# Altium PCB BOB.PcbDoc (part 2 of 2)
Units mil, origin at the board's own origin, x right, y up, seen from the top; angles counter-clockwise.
Board outline 7000 x 12000 mil, 6 copper layers (Top Layer, Int1 (GND), Int2 (Sign), Int3 (Sign), Int4 (GND2), Bottom Layer), stack 63.868 mil thick; 173 components, 165 nets, 617 pads, 174 vias.
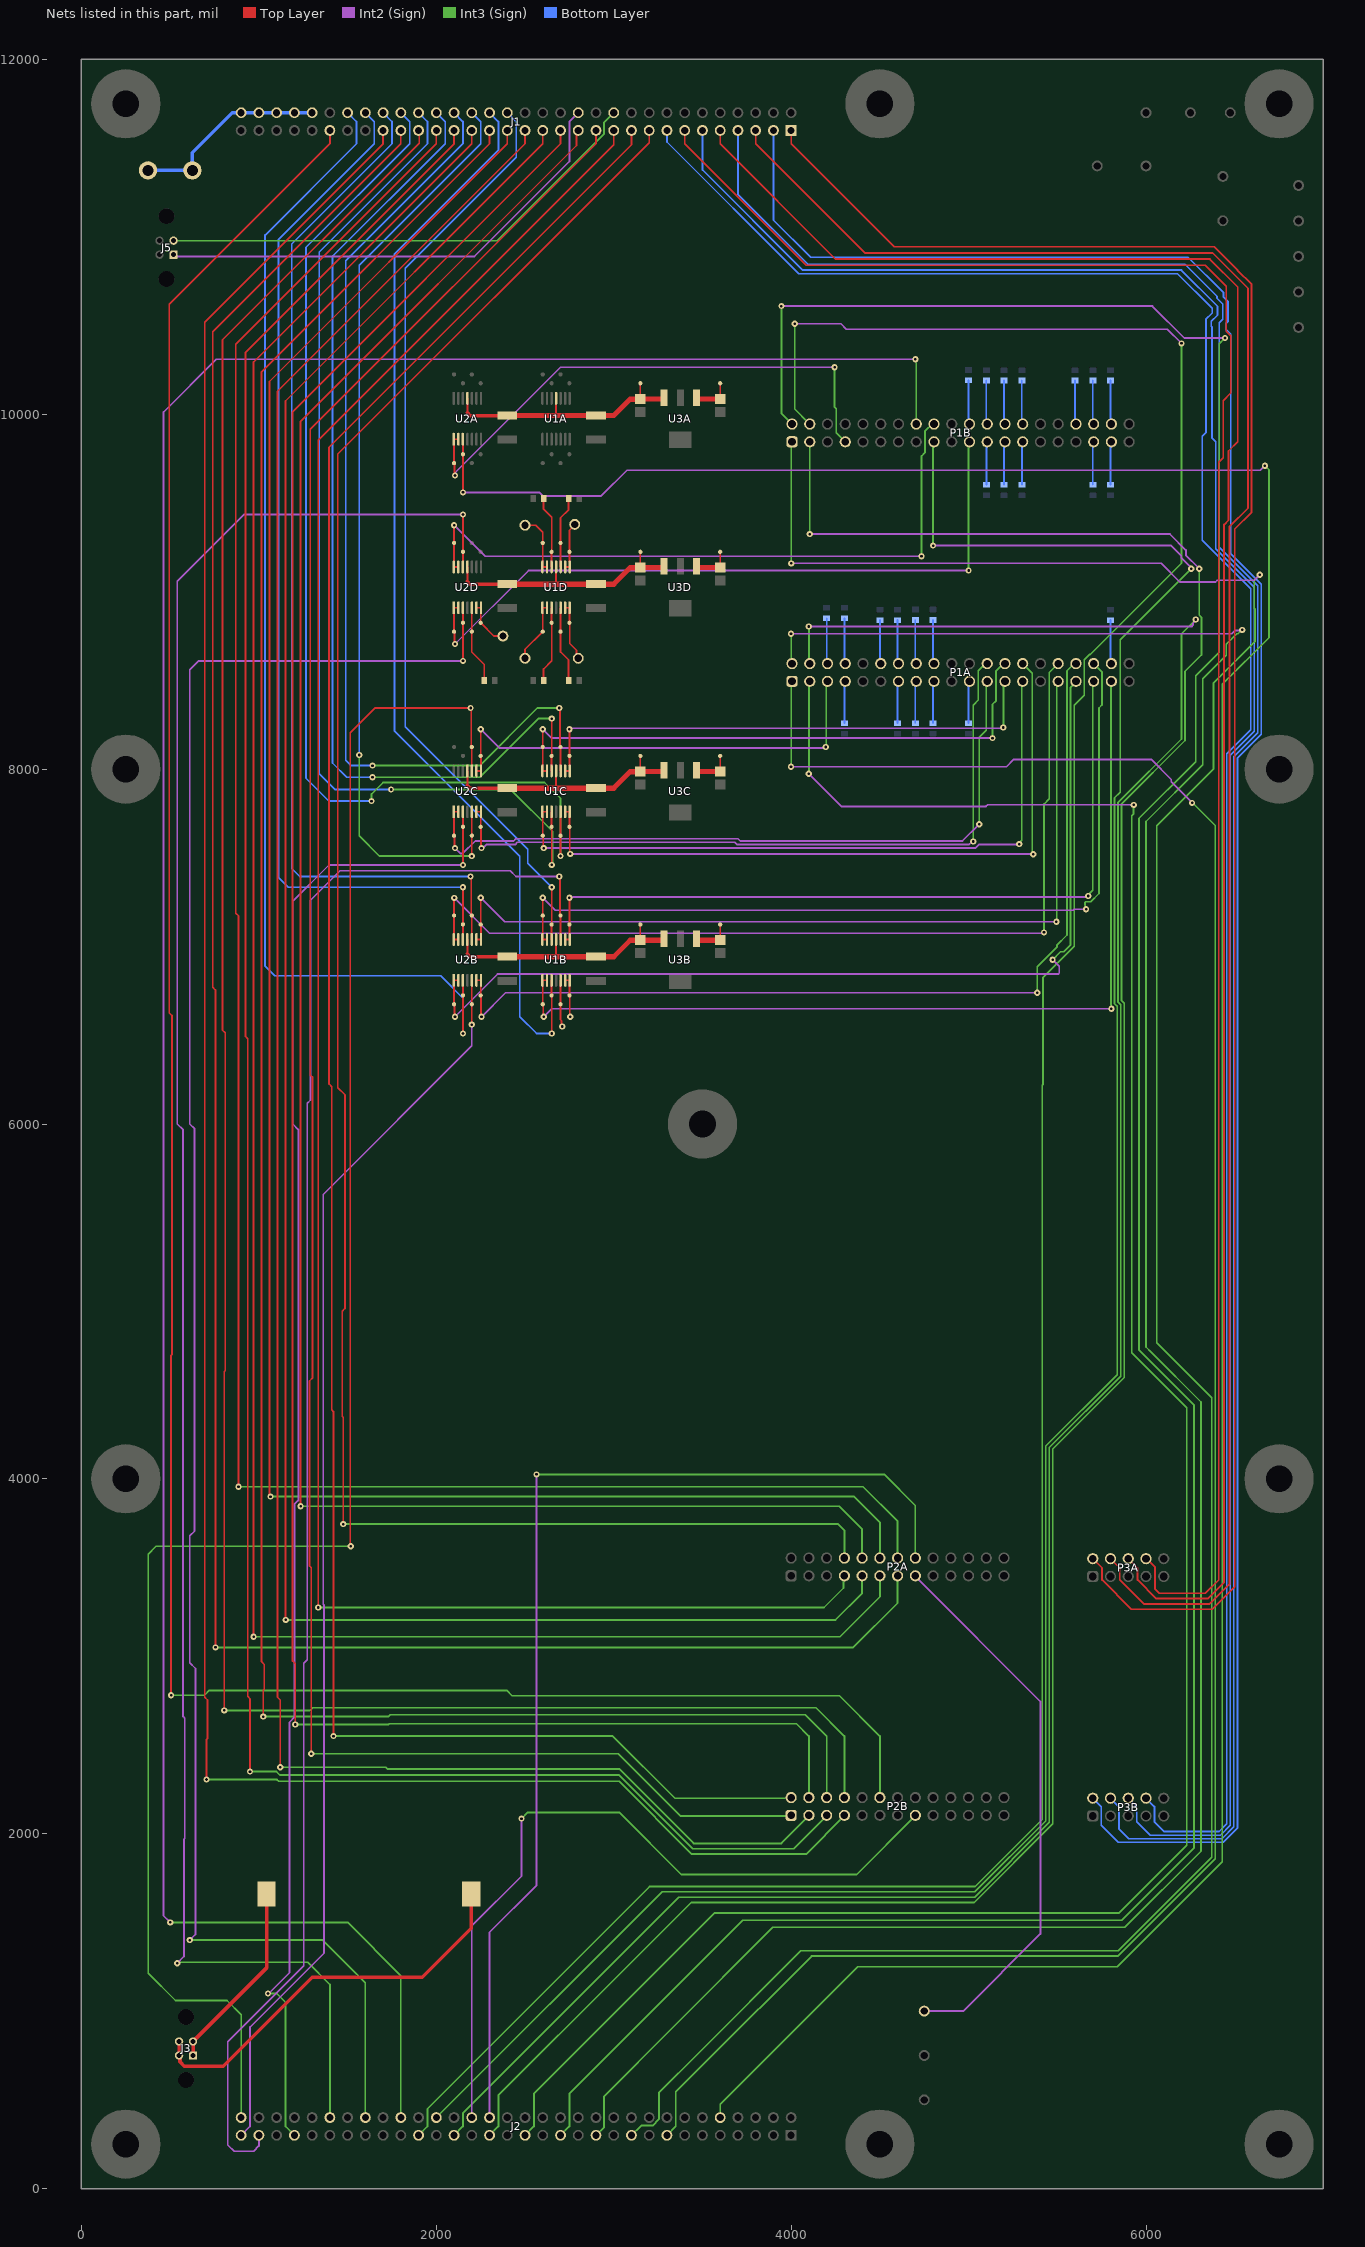
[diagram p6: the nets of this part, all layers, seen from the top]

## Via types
v1: diameter 35, hole 15, Top Layer to Bottom Layer, 157 vias
v2: diameter 25, hole 15, Top Layer to Bottom Layer, 17 vias

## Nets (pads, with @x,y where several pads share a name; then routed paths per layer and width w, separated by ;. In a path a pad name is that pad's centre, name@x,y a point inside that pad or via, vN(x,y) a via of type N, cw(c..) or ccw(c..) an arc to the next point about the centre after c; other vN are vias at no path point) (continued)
HPB_MEDIA_CURRENT: J2.64 TP6C.1 U2C.3 | length 10403.1
  Top Layer w10: v1(1517.5,3620) 1515,3622.5 1515,8205 1655.16,8345.16 v1(2193.23,8345.16) 2197.39,8340.99 2197.39,8127.61 2200.3,8124.7 2200.3,7990.45 U2C.3@2200.59,7990.16
  Int3 (Sign) w10: J2.64@900,400 900,980 820,1060 530,1060 375.86,1214.14 375.86,3575.86 420,3620 v1(1517.5,3620)
HPB_MEDIA_CURRENT_BUF: P1A.5 TP4C.1 U2C.1 U2C.2 | length 2628.8
  Top Layer w10: U2C.2@2226.18,7990.16 U2C.1@2251.77,7990.16 2251.05,7990.88 2251.05,8073.95 TP4C.1@2250,8075 v1(2250,8225)
  Int2 (Sign) w10: v1(2250,8225) 2355,8120 4190,8120 v1(4195,8125)
  Int3 (Sign) w10: v1(4195,8125) 4197.5,8127.5 4197.5,8497.5 P1A.5@4200,8500
HPB_SYNCBOX_CURRENT: J2.10 TP14A.1 U2A.10 | length 16357.4
  Top Layer w10: U2A.10@2149.41,9859.84 2149.7,9859.55 2149.7,9775.3 TP14A.1@2150,9775 v1(2150,9560)
  Int2 (Sign) w10: v1(2150,9560) 2580,9560 2600,9540 2930,9540 3075,9685 6645,9685 v1(6670,9710)
  Int3 (Sign) w10: J2.10@3600,400 3600,475 4105,980 4375,1250 5838.43,1250 6430,1841.57 6430,8478.28 6693.76,8742.05 6693.76,9686.24 v1(6670,9710)
HPB_SYNCBOX_CURRENT_BUF: P1B.7 TP12A.1 U2A.8 U2A.9 | length 3072.5
  Top Layer w10: v1(2105,9655) 2102.5,9657.5 2102.5,9722.5 TP12A.1@2100,9725 2100,9827.52 2098.23,9829.29 U2A.8@2098.23,9859.84 U2A.9@2123.82,9859.84
  Int2 (Sign) w10: v1(2105,9655) 2109.78,9659.78 2109.78,9674.78 2700,10265 v1(4245,10265)
  Int3 (Sign) w10: v1(4245,10265) 4245,10040 4254,10031 4254,9896 P1B.7@4300,9850
HPB_SYNCBOX_EN: J1.53 P2B.12 | length 13666.2
  Top Layer w10: v1(505,2780) 505,4696.32 510,4701.32 510,6610.88 495,6625.88 495,10620 1400,11525 J1.53@1400,11600
  Int3 (Sign) w10: v1(505,2780) 693.61,2780 721.11,2807.5 2396.54,2807.5 2426.54,2777.5 4272.5,2777.5 4500,2550 P2B.12@4500,2200
HPB_TEMP0: J1.44 TP13C.1 U1C.10 | length 5939.7
  Top Layer w10: U1C.10@2649.41,7759.84 2649.7,7759.55 2649.7,7675.3 TP13C.1@2650,7675 ; v1(2650.3,7460.3) TP13C.1@2650.3,7675.3
  Int3 (Sign) w10: v1(1745,7885) 2420,7885 2655,7650 2655,7465 v1(2650.3,7460.3)
  Bottom Layer w10: v1(1745,7885) 1430,7885 1340,7975 1340,8430 1340,10915 1950,11525 1950,11650 J1.44@1900,11700
HPB_TEMP0_F_BUF: P1A.27 TP11C.1 U1C.8 U1C.9 | length 3851.3
  Top Layer w10: v1(2605,7555) 2602.5,7557.5 2602.5,7622.5 TP11C.1@2600,7625 2600,7727.52 2598.23,7729.29 U1C.8@2598.23,7759.84 U1C.9@2623.82,7759.84
  Int2 (Sign) w10: v1(2605,7555) 5038.14,7555 5058.14,7575 5282.5,7575 v1(5285,7577.5)
  Int3 (Sign) w10: v1(5285,7577.5) 5285,7584.26 5300,7599.26 P1A.27@5300,8500
HPB_TEMP1: J1.46 TP17C.1 U1C.12 | length 6181
  Top Layer w10: TP17C.1@2700,7625 TP17C.1@2700.3,7625.3 ; v1(2700.3,7510.3) TP17C.1@2700.3,7625.3 ; U1C.12@2700.59,7759.84 2700.3,7759.55 TP17C.1@2700.3,7625.3
  Int3 (Sign) w10: v1(1635,7820) 1635,7860 1700,7925 2610,7925 2700.3,7834.7 v1(2700.3,7510.3)
  Bottom Layer w10: v1(1635,7820) 1395,7820 1265,7950 1265,8430 1265,10940 1850,11525 1850,11650 J1.46@1800,11700
HPB_TEMP1_F_BUF: P1A.28 TP15C.1 U1C.13 U1C.14 | length 3983.7
  Top Layer w10: U1C.13@2726.18,7759.84 U1C.14@2751.77,7759.84 2751.05,7759.12 2751.05,7676.05 TP15C.1@2750,7675 2752.5,7672.5 2752.5,7525 v1(2755,7522.5)
  Int2 (Sign) w10: v1(2755,7522.5) 2756.25,7521.25 5363.75,7521.25 v1(5365,7520)
  Int3 (Sign) w10: P1A.28@5300,8600 5358.5,8541.5 5358.5,7538.36 5360.22,7536.65 5360.22,7524.78 v1(5365,7520)
HPB_TEMP2: J1.48 TP6B.1 U2B.3 | length 5898.8
  Top Layer w10: v1(2192.93,7394.86) 2197.39,7390.4 2197.39,7179.08 TP6B.1@2200.74,7175.74 ; TP6B.1@2200,7175 2200.3,7174.7 2200.3,7040.45 U2B.3@2200.59,7040.16
  Bottom Layer w10: J1.48@1700,11700 1750,11650 1750,11525 1185,10960 1185,7440 1230.14,7394.86 v1(2192.93,7394.86)
HPB_TEMP2_F_BUF: P1A.31 TP4B.1 U2B.1 U2B.2 | length 4924.2
  Top Layer w10: U2B.2@2226.18,7040.16 U2B.1@2251.77,7040.16 2251.05,7040.88 2251.05,7123.95 TP4B.1@2250,7125 v1(2250,7275)
  Int2 (Sign) w10: v1(2250,7275) 2385,7140 v1(5495,7140)
  Int3 (Sign) w10: v1(5495,7140) 5497.5,7142.5 5497.5,8497.5 P1A.31@5500,8500
HPB_TEMP3: J1.50 TP10B.1 U2B.5 | length 5911.6
  Top Layer w10: U2B.5@2149.41,7040.16 2149.7,7040.45 2149.7,7124.7 TP10B.1@2150,7125 ; v1(2149.7,7334.7) 2149.85,7334.56 2149.85,7126.33 TP10B.1@2150.59,7125.59
  Bottom Layer w10: J1.50@1600,11700 1650,11650 1650,11525 1110,10985 1110,7390 1165.3,7334.7 v1(2149.7,7334.7)
HPB_TEMP3_F_BUF: P1A.32 TP8B.1 U2B.6 U2B.7 | length 5221.2
  Top Layer w10: v1(2100.48,7274.52) 2100.24,7274.28 2100.24,7175.24 2098.95,7173.95 2098.95,7040.88 U2B.7@2098.23,7040.16 U2B.6@2123.82,7040.16
  Int2 (Sign) w10: v1(2100.48,7274.52) 2300,7075 5420,7075 v1(5425,7080)
  Int3 (Sign) w10: v1(5425,7080) 5425,7802.91 5455,7832.91 5455,8545 5500,8590 P1A.32@5500,8600
HPB_TEMP4: J1.52 TP14B.1 U2B.10 | length 6733.6
  Top Layer w10: U2B.10@2149.41,6809.84 2149.7,6809.55 2149.7,6725.3 TP14B.1@2150,6725 ; v1(2150.15,6510.15) TP14B.1@2150.15,6725.15
  Bottom Layer w10: J1.52@1500,11700 1550,11650 1550,11525 1035,11010 1035,6890 1090,6835 2025,6835 2150.15,6709.85 v1(2150.15,6510.15)
HPB_TEMP4_F_BUF: P1A.33 TP12B.1 U2B.8 U2B.9 | length 5468.9
  Top Layer w10: v1(2105,6605) 2102.5,6607.5 2102.5,6672.5 TP12B.1@2100,6675 2100,6777.52 2098.23,6779.29 U2B.8@2098.23,6809.84 U2B.9@2123.82,6809.84
  Int2 (Sign) w10: v1(2105,6605) 2345,6845 5505.58,6845 5511.43,6850.86 5511.43,6888.57 v1(5473.72,6926.28)
  Int3 (Sign) w10: v1(5473.72,6926.28) 5517.91,6970.47 5535.59,6970.47 5575,7009.88 5575,8461.19 5600,8486.19 P1A.33@5600,8500
HPB_VICOR1_TEMP: J1.38 TP18C.1 U2C.12 | length 5312.2
  Top Layer w10: v1(2200,7510) TP18C.1@2200,7625 2200.3,7625.3 2200.3,7759.55 U2C.12@2200.59,7759.84
  Int3 (Sign) w10: v1(1565,8080) 1565,7625 1680,7510 v1(2200,7510)
  Bottom Layer w10: v1(1565,8080) 1565,8430 1565,10840 2250,11525 2250,11650 J1.38@2200,11700
HPB_VICOR1_TEMP_F_BUF: P1A.24 TP16C.1 U2C.13 U2C.14 | length 4068.2
  Top Layer w10: U2C.13@2226.18,7759.84 U2C.14@2251.77,7759.84 2251.77,7729.29 2250,7727.52 TP16C.1@2250,7675 2252.5,7672.5 2252.5,7557.5 v1(2255,7555)
  Int2 (Sign) w10: v1(2255,7555) 2260.96,7555 2280.96,7575 2443.86,7575 2456.36,7587.5 3682.78,7587.5 3695.28,7575 5001.52,7575 5019.02,7592.5 v1(5025.78,7592.5)
  Int3 (Sign) w10: v1(5025.78,7592.5) 5025.78,8360.78 5055,8390 5055,8555 P1A.24@5100,8600
HPB_VICOR2_TEMP: J1.40 TP5C.1 U1C.3 | length 5652.1
  Top Layer w10: v1(2693.23,8345.16) 2697.39,8340.99 2697.39,8127.61 TP5C.1@2700,8125 ; TP5C.1@2700.3,8124.7 2700.3,7990.45 U1C.3@2700.59,7990.16
  Int3 (Sign) w10: v1(1640,8020) 2245,8020 2570.16,8345.16 v1(2693.23,8345.16)
  Bottom Layer w10: v1(1640,8020) 1520,8020 1490,8050 1490,8430 1490,10865 2150,11525 2150,11650 J1.40@2100,11700
HPB_VICOR2_TEMP_F_BUF: P1A.25 TP3C.1 U1C.1 U1C.2 | length 2977.4
  Top Layer w10: U1C.2@2726.18,7990.16 U1C.1@2751.77,7990.16 2751.77,8020.71 2750,8022.48 TP3C.1@2750,8075 v1(2750,8225)
  Int2 (Sign) w10: v1(2750,8225) 2755,8230 5190,8230 v1(5195,8235)
  Int3 (Sign) w10: v1(5195,8235) 5197.5,8237.5 5197.5,8497.5 P1A.25@5200,8500
HPB_VICOR3_TEMP: J1.42 TP9C.1 U1C.5 | length 5648.1
  Top Layer w10: U1C.5@2649.41,7990.16 2649.7,7990.45 2649.7,8074.7 TP9C.1@2650,8075 ; v1(2650,8285) 2650,8076.77 TP9C.1@2650.89,8075.89
  Int3 (Sign) w10: v1(1640,7955) 2245,7955 2575,8285 v1(2650,8285)
  Bottom Layer w10: v1(1640,7955) 1495,7955 1415,8035 1415,8430 1415,10890 2050,11525 2050,11650 J1.42@2000,11700
HPB_VICOR3_TEMP_F_BUF: P1A.26 TP7C.1 U1C.6 U1C.7 | length 3268.8
  Top Layer w10: v1(2600,8225) TP7C.1@2600,8125 2600,8022.48 2598.23,8020.71 U1C.7@2598.23,7990.16 U1C.6@2623.82,7990.16
  Int2 (Sign) w10: v1(2600,8225) 2650,8175 v1(5135,8175)
  Int3 (Sign) w10: v1(5135,8175) 5135,8365.41 5155,8385.41 5155,8555 P1A.26@5200,8600
I2C_SCL: J1.26 J5.1 | length 2752.7
  Int2 (Sign) w10: J5.1@518.74,10900 528.74,10890 2215,10890 2750,11425 2750,11650 J1.26@2800,11700
I2C_SDA: J1.22 J5.2 | length 2817.7
  Int3 (Sign) w10: J5.2@518.74,10978.74 2343.1,10978.74 2945.51,11581.15 2945.51,11645.51 J1.22@3000,11700
IGB_TEMP_F: J2.57 TP14C.1 U2C.10 | length 8476.9
  Top Layer w10: U2C.10@2149.41,7759.84 2149.7,7759.55 2149.7,7675.3 TP14C.1@2150,7675 v1(2150,7460)
  Int2 (Sign) w10: v1(1050.88,1099.12) 1054.41,1099.12 1172.5,1217.21 1172.5,2628.46 1200,2655.96 1200,3855.96 1222.5,3878.46 1222.5,5968.5 1191,6000 1191,7256 1395,7460 v1(2150,7460)
  Int3 (Sign) w10: v1(1050.88,1099.12) 1100.88,1099.12 1150,1050 1150,350 J2.57@1200,300
IGB_TEMP_F_BUF: P1A.23 TP12C.1 U2C.8 U2C.9 | length 4105.9
  Top Layer w10: v1(2105,7555) 2102.5,7557.5 2102.5,7622.5 TP12C.1@2100,7625 2100,7727.52 2098.23,7729.29 U2C.8@2098.23,7759.84 U2C.9@2123.82,7759.84
  Int2 (Sign) w10: v1(2105,7555) 2135,7525 2150,7525 2220,7595 2435.58,7595 2448.08,7607.5 3700.29,7607.5 3712.79,7595 4965,7595 v1(5060,7690)
  Int3 (Sign) w10: v1(5060,7690) 5060,8180 5100,8220 P1A.23@5100,8500
INPUT_FET_LEFT_TEMP_F: J2.63 TP18B.1 U2B.12 | length 7052.9
  Top Layer w10: TP18B.1@2200,6675 2200.3,6675.3 2200.3,6809.55 U2B.12@2200.59,6809.84 ; v1(2200.15,6560.15) TP18B.1@2200.15,6675.15
  Int2 (Sign) w10: J2.63@900,300 950,350 950,909.85 1367.5,1327.35 1367.5,3288.46 1362.5,3293.46 1362.5,5602.5 2200.15,6440.15 v1(2200.15,6560.15)
INPUT_FET_LEFT_TEMP_F_BUF: P1A.34 TP16B.1 U2B.13 U2B.14 | length 5369.7
  Top Layer w10: U2B.13@2226.18,6809.84 U2B.14@2251.77,6809.84 2251.77,6779.29 2250,6777.52 TP16B.1@2250,6725 2252.5,6722.5 2252.5,6607.5 v1(2255,6605)
  Int2 (Sign) w10: v1(2255,6605) 2390,6740 v1(5387.5,6740)
  Int3 (Sign) w10: v1(5387.5,6740) 5387.5,6886.02 5497.79,6996.31 5497.79,7007.79 5555,7065 5555,8555 P1A.34@5600,8600
INPUT_FET_RIGHT_TEMP_F: J2.61 TP5B.1 U1B.3 | length 9313.1
  Top Layer w10: v1(2693.23,7395.16) 2697.39,7390.99 2697.39,7177.61 TP5B.1@2700,7175 ; TP5B.1@2700.3,7174.7 2700.3,7040.45 U1B.3@2700.59,7040.16
  Int2 (Sign) w10: J2.61@1000,300 1000,240 970,210 860,210 825,245 825,827.28 1252.5,1254.78 1252.5,2961.11 1272.5,2981.11 1272.5,6116.5 1291,6135 1291,7261 1457.36,7427.36 2416.86,7427.36 2449.07,7395.16 v1(2693.23,7395.16)
INPUT_FET_RIGHT_TEMP_F_BUF: P1A.35 TP3B.1 U1B.1 U1B.2 | length 4415.7
  Top Layer w10: U1B.2@2726.18,7040.16 U1B.1@2751.77,7040.16 2751.77,7070.71 2750,7072.48 TP3B.1@2750,7125 v1(2750,7275)
  Int2 (Sign) w10: v1(2750,7275) 2755,7280 5670,7280 v1(5675,7285)
  Int3 (Sign) w10: v1(5675,7285) 5675,7291.57 5700,7316.57 P1A.35@5700,8500
IPB1_BOARD_TEMP: J1.34 TP9B.1 U1B.5 | length 5280.9
  Top Layer w10: U1B.5@2649.41,7040.16 2649.7,7040.45 2649.7,7124.7 TP9B.1@2650,7125 ; v1(2650,7335) 2650,7126.77 TP9B.1@2650.89,7125.89
  Bottom Layer w10: J1.34@2400,11700 2450,11650 2450,11447.84 1825,10822.84 1825,8239.29 2515,7549.29 2515,7470 v1(2650,7335)
IPB1_BOARD_TEMP_BUF: P1A.36 TP7B.1 U1B.6 U1B.7 | length 4824.3
  Top Layer w10: v1(2600,7275) TP7B.1@2600,7175 2600,7072.48 2598.23,7070.71 U1B.7@2598.23,7040.16 U1B.6@2623.82,7040.16
  Int2 (Sign) w10: v1(2600,7275) 2670,7205 5590,7205 5595,7210 v1(5662.5,7210)
  Int3 (Sign) w10: v1(5662.5,7210) 5657.72,7214.78 5657.72,7234.61 5655.68,7236.64 5655.68,7246.64 5661.54,7252.5 5688.46,7252.5 5735,7299.04 5735,8345 5751.5,8361.5 5751.5,8548.5 P1A.36@5700,8600
IPB1_CHA_CURRENT_SET: J1.1 P3A.2 | length 11389.1
  Top Layer w10: J1.1@4000,11600 4000,11525 4580,10945 6385,10945 6515,10815 6515,10812.43 6595,10732.43 6595,9448.46 6500,9353.46 6500,3392.72 6372.28,3265 5917.85,3265 5752.52,3430.33 5752.52,3497.48 P3A.2@5700,3550
IPB1_CHA_FET_EN: J1.21 P2A.7 | length 12087.3
  Top Layer w10: v1(1335,3275) 1335,9854.91 3000,11519.91 J1.21@3000,11600
  Int3 (Sign) w10: v1(1335,3275) 4185,3275 4295,3385 4295,3445 P2A.7@4300,3450
IPB1_CHA_I: J2.15 P1A.1 | length 12729.4
  Int2 (Sign) w10: v1(3998.75,8013.75) 5213.75,8013.75 5255,8055 6028.46,8055 6141.84,7941.62 6141.84,7928.16 v1(6260,7810)
  Int3 (Sign) w10: J2.15@3300,300 3350,350 3350,545 3522.5,717.5 4115,1310 5841.86,1310 6390,1858.14 6390,7682.32 6262.32,7810 v1(6260,7810) ; v1@4000,8015 P1A.1@4000,8500
IPB1_CHA_RLY_EN: J1.17 P2A.8 | length 11606.3
  Top Layer w10: v1(1475,3745) 1475,4346.12 1470,4351.12 1470,4945.47 1485,4960.47 1485,6164.17 1445,6204.17 1445,9776.57 3200,11531.57 J1.17@3200,11600
  Int3 (Sign) w10: v1(1475,3745) 4265,3745 4300,3710 P2A.8@4300,3550
IPB1_CHB_CURRENT_SET: J1.5 P3A.4 | length 11396.5
  Top Layer w10: J1.5@3800,11600 3800,11525 4415,10910 6375,10910 6575,10710 6575,9470.89 6470,9365.89 6470,3405.15 6359.85,3295 5987.85,3295 5852.52,3430.33 5852.52,3497.48 P3A.4@5800,3550
IPB1_CHB_FET_EN: J1.29 P2A.9 | length 12402.2
  Top Layer w10: v1(1151,3205) 1150,3206 1150,10075 2600,11525 J1.29@2600,11600
  Int3 (Sign) w10: v1(1151,3205) 4250,3205 4400,3355 P2A.9@4400,3450
IPB1_CHB_I: J2.23 P1A.2 | length 14135.1
  Int2 (Sign) w10: v1(3998.75,8763.75) 6482.79,8763.75 6500,8780.96 6538.46,8780.96 v1(6542.5,8785)
  Int3 (Sign) w10: J2.23@2900,300 2945.51,345.51 2945.51,520.51 3332.5,907.5 3897.28,1472.28 5857.28,1472.28 5880.42,1472.28 6310,1901.86 6310,4433.22 6030,4713.22 6000,4743.22 6000,7705.15 6320,8025.15 6320,8509.71 6452.5,8642.21 6452.5,8704.04 6511.46,8763 6518.54,8763 6540.53,8785 v1(6542.5,8785) ; P1A.2@4000,8600 v1@4000,8765
IPB1_CHB_RLY_EN: J1.25 P2A.10 | length 11787.1
  Top Layer w10: v1(1235,3845) 1235,9960 2790.32,11515.32 2790.32,11590.32 J1.25@2800,11600
  Int3 (Sign) w10: v1(1235,3845) 4270,3845 4400,3715 P2A.10@4400,3550
IPB1_CHC_CURRENT_SET: J1.9 P3A.6 | length 11369.9
  Top Layer w10: J1.9@3600,11600 3600,11525 4250,10875 6360,10875 6517.5,10717.5 6517.5,9845.96 6465,9793.46 6465,9403.31 6440,9378.31 6440,3417.57 6347.43,3325 6057.85,3325 5952.52,3430.33 5952.52,3497.48 P3A.6@5900,3550
IPB1_CHC_FET_EN: J1.37 P2A.11 | length 12738.4
  Top Layer w10: v1(970,3110) 970,10295 2200,11525 J1.37@2200,11600
  Int3 (Sign) w10: v1(970,3110) 4275,3110 4500.86,3335.86 4500.86,3379.81 4500,3380.66 P2A.11@4500,3450
IPB1_CHC_I: J2.31 P1A.3 | length 12950.7
  Int2 (Sign) w10: v1(4098.75,7973.75) 4282.5,7790 5097.87,7790 5107.87,7800 5930,7800 v1(5931.27,7798.73)
  Int3 (Sign) w10: J2.31@2500,300 2550,350 2550,535 3127.5,1112.5 3567.28,1552.28 5847.28,1552.28 6230,1935 6230,4400 5920,4710 5920,7738.28 5930,7748.28 5930,7797.47 v1(5931.27,7798.73) ; v1@4100,7975 P1A.3@4100,8500
IPB1_CHC_RLY_EN: J1.33 P2A.12 | length 11957.2
  Top Layer w10: v1(1065,3900) 1060,3905 1060,10185 2400,11525 J1.33@2400,11600
  Int3 (Sign) w10: v1(1065,3900) 4355,3900 4500,3755 P2A.12@4500,3550
IPB1_CHD_CURRENT_SET: J1.13 P3A.8 | length 11385.8
  Top Layer w10: J1.13@3400,11600 3400,11525 4085,10840 6335,10840 6452.5,10722.5 6452.5,10468.46 6477.5,10443.46 6477.5,10120.04 6435,10077.54 6435,9754.11 6410,9729.11 6410,3430 6335,3355 6075,3355 6050,3380 6050,3505 6005,3550 P3A.8@6000,3550
IPB1_CHD_FET_EN: J1.45 P2A.13 | length 13093.8
  Top Layer w10: v1(755,3050) 755,6755.41 740,6770.41 740,10465 1800,11525 J1.45@1800,11600
  Int3 (Sign) w10: v1(755,3050) 4350,3050 4600,3300 P2A.13@4600,3450
IPB1_CHD_I: J2.39 P1A.4 | length 13675.6
  Int2 (Sign) w10: v1(4098.75,8803.75) 6257.31,8803.75 6264.38,8810.82 6264.38,8820.75 6280,8836.37 v1(6280,8843.14)
  Int3 (Sign) w10: J2.39@2100,300 2150,350 2150,425 2982.5,1257.5 3367.28,1642.28 5033.85,1642.28 5455,2063.43 5455,4176.72 5857.5,4579.22 5857.5,6671.75 5842.5,6686.75 5842.5,7812.5 6200,8170 6200,8763.14 v1(6280,8843.14) ; P1A.4@4100,8600 v1@4100,8805
IPB1_CHD_RLY_EN: J1.41 P2A.14 | length 12125
  Top Layer w10: v1(885,3955) 885,7172.91 870,7187.91 870,10395 2000,11525 J1.41@2000,11600
  Int3 (Sign) w10: v1(885,3955) 4405,3955 4600,3760 P2A.14@4600,3550
IPB1_RESET: J2.36 P2A.16 | length 6242.3
  Int2 (Sign) w10: J2.36@2300,400 2300,1445 2565,1710 v1(2565,4025)
  Int3 (Sign) w10: v1(2565,4025) 4525,4025 4700,3850 P2A.16@4700,3550
IPB2_BOARD_TEMP: J1.36 TP13B.1 U1B.10 | length 6169.5
  Top Layer w10: U1B.10@2649.41,6809.84 2649.7,6809.55 2649.7,6725.3 TP13B.1@2650,6725 v1(2650,6510)
  Bottom Layer w10: J1.36@2300,11700 2350,11650 2350,11489.26 1765,10904.26 1765,8214.29 2470,7509.29 2470,6605 2565,6510 v1(2650,6510)
IPB2_BOARD_TEMP_BUF: P1A.37 TP11B.1 U1B.8 U1B.9 | length 5303.9
  Top Layer w10: v1(2605,6605) 2602.5,6607.5 2602.5,6672.5 TP11B.1@2600,6675 2600,6777.52 2598.23,6779.29 U1B.8@2598.23,6809.84 U1B.9@2623.82,6809.84
  Int2 (Sign) w10: v1(2605,6605) 2650,6650 v1(5805,6650)
  Int3 (Sign) w10: P1A.37@5800,8500 5802.5,8497.5 5802.5,6652.5 v1(5805,6650)
IPB2_CHA_CURRENT_SET: J1.3 P3B.2 | length 13031
  Bottom Layer w10: J1.3@3900,11600 3900,11095 4110,10885 6236.57,10885 6437.18,10684.39 6437.18,10660.1 6462.82,10634.45 6462.82,10523.79 6452.5,10513.46 6452.5,10475.89 6477.5,10450.89 6477.5,9214.07 6650,9041.57 6650,8196.98 6515,8061.98 6515,2030.15 6436.49,1951.64 5843.36,1951.64 5747.48,2047.52 5747.48,2152.52 P3B.2@5700,2200
IPB2_CHA_FET_EN: J1.23 P2B.1 | length 12683.4
  Top Layer w10: v1(1295,2450) 1295,3499.04 1285,3509.04 1285,4551.32 1302.5,4568.82 1302.5,6263.38 1290,6275.88 1290,9915 2900,11525 J1.23@2900,11600
  Int3 (Sign) w10: v1(1295,2450) 3025,2450 3375,2100 P2B.1@4000,2100
IPB2_CHA_I: J2.19 P1B.1 | length 15001.3
  Int2 (Sign) w10: v1(4000,9160) 6085,9160 6190,9055 6391.62,9055 6401.62,9065 6610,9065 v1(6641.26,9096.26)
  Int3 (Sign) w10: J2.19@3100,300 3154.49,354.49 3218.85,354.49 3254.49,390.12 3254.49,539.49 3477.5,762.5 4055,1340 5843.58,1340 6370,1866.42 6370,4458.08 6060,4768.08 6060,7680.29 6380,8000.29 6380,8484.85 6615,8719.85 6615,8901.71 6610,8906.71 6610,9065 v1(6641.26,9096.26) ; v1(4000,9160) P1B.1@4000,9850
IPB2_CHA_RLY_EN: J1.19 P2B.2 | length 12491.6
  Top Layer w10: v1(1420,2550) 1420,4378.8 1410,4388.8 1410,6210.84 1395,6225.84 1395,9814.91 3100,11519.91 J1.19@3100,11600
  Int3 (Sign) w10: v1(1420,2550) 2995,2550 3345,2200 P2B.2@4000,2200
IPB2_CHB_CURRENT_SET: J1.7 P3B.4 | length 12983.2
  Bottom Layer w10: J1.7@3700,11600 3700,11240 4095,10845 6220,10845 6400,10665 6400,10654.85 6432.82,10622.03 6432.82,10536.21 6412.5,10515.89 6412.5,9854.5 6412.82,9854.17 6412.82,9250.46 6630,9033.28 6630,8205.27 6520,8095.27 6495,8070.27 6495,2038.43 6428.21,1971.64 5903.36,1971.64 5847.48,2027.52 5847.48,2152.52 P3B.4@5800,2200
IPB2_CHB_FET_EN: J1.31 P2B.3 | length 13031.4
  Top Layer w10: v1(1120,2375) 1120,2753.61 1105,2768.61 1105,10130 2500,11525 J1.31@2500,11600
  Int3 (Sign) w10: v1(1120,2375) 1714.3,2375 1724.3,2365 3030,2365 3450,1945 3945,1945 P2B.3@4100,2100
IPB2_CHB_I: J2.27 P1B.2 | length 16447
  Int2 (Sign) w10: v1(3945,10610) 6035.96,10610 6215.96,10430 v1(6445,10430)
  Int3 (Sign) w10: J2.27@2700,300 2750,350 2750,535 3227.5,1012.5 3727.28,1512.28 5448.85,1512.28 5863.85,1512.28 6270,1918.43 6270,4416.66 5990,4696.66 5960,4726.66 5960,7721.72 6280,8041.72 6280,8526.27 6412.5,8658.77 6412.5,10397.5 v1(6445,10430) ; v1(3945,10610) 3945,10005 P1B.2@4000,9950
IPB2_CHB_RLY_EN: J1.27 P2B.4 | length 12892.7
  Top Layer w10: v1(1205,2615) 1205,2958.61 1190,2973.61 1190,10015 2700,11525 J1.27@2700,11600
  Int3 (Sign) w10: v1(1205,2615) 1729.3,2615 1734.3,2620 4030,2620 4100,2550 P2B.4@4100,2200
IPB2_CHC_CURRENT_SET: J1.11 P3B.6 | length 12911
  Bottom Layer w10: J1.11@3500,11600 3500,11377.43 4064.7,10812.72 6199.7,10812.72 6402.82,10609.6 6402.82,10558.46 6367.82,10523.46 6367.82,10496.54 6372.5,10491.86 6372.5,9866.21 6392.82,9845.89 6392.82,9242.17 6610,9025 6610,8213.55 6500,8103.55 6475,8078.55 6475,2046.72 6419.93,1991.64 6023.36,1991.64 5947.48,2067.52 5947.48,2152.52 P3B.6@5900,2200
IPB2_CHC_FET_EN: J1.39 P2B.5 | length 13253.9
  Top Layer w10: v1(950,2350) 950,2761.11 937.5,2773.61 937.5,6480.88 925,6493.38 925,10350 2100,11525 J1.39@2100,11600
  Int3 (Sign) w10: v1(950,2350) 1099.04,2350 1119.04,2330 3030,2330 3445,1915 4015,1915 P2B.5@4200,2100
IPB2_CHC_I: J2.35 P1B.3 | length 14260.8
  Int2 (Sign) w10: v1(4105,9325) 6135,9325 6225.11,9234.89 6225.11,9205.85 6300,9130.96 v1(6300,9130)
  Int3 (Sign) w10: J2.35@2300,300 2350,350 2350,525 3032.5,1207.5 3437.28,1612.28 5032.13,1612.28 5475,2055.15 5475,4168.43 5877.5,4570.93 5877.5,6680.03 5862.5,6695.03 5862.5,7804.22 6220,8161.72 6220,8551.13 6312.5,8643.63 6312.5,8856.6 6300,8869.1 v1(6300,9130) ; v1(4105,9325) P1B.3@4105,9848.59
IPB2_CHC_RLY_EN: J1.35 P2B.6 | length 13059.4
  Top Layer w10: v1(1025,2660) 1025,2807.69 1030,2812.69 1030,2953.61 1015,2968.61 1015,10240 2300,11525 J1.35@2300,11600
  Int3 (Sign) w10: v1(1025,2660) 1729.3,2660 1739.3,2670 4080,2670 4200,2550 P2B.6@4200,2200
IPB2_CHD_CURRENT_SET: J1.15 P3B.8 | length 12860.9
  Bottom Layer w10: J1.15@3300,11600 3300,11535 4042.28,10792.72 6177.28,10792.72 6372.82,10597.18 6372.82,10570.89 6337.82,10535.89 6337.82,9896.82 6317.5,9876.5 6317.5,9289.21 6590,9016.71 6590,8221.84 6480,8111.84 6455,8086.84 6455,2055 6411.64,2011.64 6103.36,2011.64 6047.48,2067.52 6047.48,2152.52 P3B.8@6000,2200
IPB2_CHD_FET_EN: J1.47 P2B.7 | length 13577.6
  Top Layer w10: v1(705,2305) 705,2530.19 710,2535.19 710,2753.61 695,2768.61 695,10520 1700,11525 J1.47@1700,11600
  Int3 (Sign) w10: v1(705,2305) 1101.61,2305 1111.61,2295 3030,2295 3440,1885 4085,1885 P2B.7@4300,2100
IPB2_CHD_I: J2.43 P1B.4 | length 15776.7
  Int2 (Sign) w10: v1(4020,10510) 4280.96,10510 4310.96,10480 6120,10480 v1(6200,10400)
  Int3 (Sign) w10: J2.43@1900,300 1950,350 1950,450 2870,1370 3202.28,1702.28 5037.28,1702.28 5415,2080 5415,6217.81 5420,6222.81 5420,6826.6 5595,7001.6 5595,8360 5651.5,8416.5 5651.5,8615.86 5681.15,8645.51 5684.56,8645.51 6200,9160.95 v1(6200,10400) ; v1(4020,10510) 4020,10030 P1B.4@4100,9950
IPB2_CHD_RLY_EN: J1.43 P2B.8 | length 13291.1
  Top Layer w10: v1(805,2695) 805,4605.07 810,4610.07 810,6513.38 795,6528.38 795,10420 1903.14,11528.14 1903.14,11596.86 J1.43@1900,11600
  Int3 (Sign) w10: v1(805,2695) 1288.03,2695 1303.03,2710 4140,2710 4300,2550 P2B.8@4300,2200
IPB2_RESET: J2.38 P2B.15 | length 4317.1
  Int2 (Sign) w10: J2.38@2200,400 2200,1480 2480,1760 v1(2480,2085)
  Int3 (Sign) w10: v1(2480,2085) 2515,2120 3030,2120 3380,1770 4370,1770 P2B.15@4700,2100
MVC_L_CURRENT: J2.46 P1B.16 | length 15480.1
  Int2 (Sign) w10: v1(500,1500) 462.5,1537.5 462.5,10012.5 760,10310 v1(4700,10310)
  Int3 (Sign) w10: v1(500,1500) 1500,1500 1800,1200 J2.46@1800,400 ; v1(4700,10310) 4700,10303.24 4705,10298.24 P1B.16@4705,9945
MVC_L_VOLTAGE: J2.54 TP10D.1 U2D.5 | length 11549
  Top Layer w10: U2D.5@2149.41,9140.16 2149.7,9140.45 2149.7,9224.7 TP10D.1@2150,9225 ; v1(2150,9435) 2150,9226.77 TP10D.1@2150.89,9225.89
  Int2 (Sign) w10: v1(540,1270) 577.5,1307.5 577.5,1967.98 582.5,1972.98 582.5,2651.04 572.5,2661.04 572.5,5967.5 540,6000 540,8940 540,9060 915,9435 v1(2150,9435)
  Int3 (Sign) w10: v1(540,1270) 545,1275 1275,1275 1400,1150 J2.54@1400,400
MVC_L_VOLTAGE_BUF: P1B.18 TP8D.1 U2D.6 U2D.7 | length 3745.4
  Top Layer w10: TP8D.1@2100,9275 2098.95,9273.95 2098.95,9140.88 U2D.7@2098.23,9140.16 U2D.6@2123.82,9140.16 ; TP8D.1@2100.36,9275.36 v1(2100.36,9375.36)
  Int2 (Sign) w10: v1(2100.36,9375.36) 2275.72,9200 v1(4735,9200)
  Int3 (Sign) w10: v1(4735,9200) 4735,9765 4754,9784 4754,9904 P1B.18@4800,9950
MVC_R_CURRENT: J2.42 P1B.17 | length 13646.9
  Int2 (Sign) w10: v1(4800,9260) 6142.5,9260 6198.86,9203.64 6198.86,9191.14 6255,9135 v1(6255,9130)
  Int3 (Sign) w10: J2.42@2000,400 3272.28,1672.28 5035.56,1672.28 5435,2071.72 5435,4185 5837.5,4587.5 5837.5,6663.46 5822.5,6678.46 5822.5,7838.06 5855,7870.56 5855,8730 v1(6255,9130) ; v1(4800,9260) P1B.17@4800,9850
MVC_R_VOLTAGE: J2.50 TP14D.1 U2D.10 | length 10920.3
  Top Layer w10: U2D.10@2149.41,8909.84 2149.7,8909.55 2149.7,8825.3 TP14D.1@2150,8825 ; v1(2150.3,8610.3) TP14D.1@2150.3,8825.3
  Int2 (Sign) w10: v1(610,1400) 642.5,1432.5 642.5,2931.11 610,2963.61 610,3678.27 637.5,3705.77 637.5,5972.5 610,6000 610,8560 660.29,8610.3 v1(2150.3,8610.3)
  Int3 (Sign) w10: v1(610,1400) 1360,1400 1600,1160 J2.50@1600,400
MVC_R_VOLTAGE_BUF: P1B.21 TP12D.1 U2D.8 U2D.9 | length 4029.6
  Top Layer w10: TP12D.1@2100,8775 2100,8877.52 2098.23,8879.29 U2D.8@2098.23,8909.84 U2D.9@2123.82,8909.84 ; TP12D.1@2100.36,8775.36 2102.61,8773.12 2102.61,8708.12 v1(2105.36,8705.36)
  Int2 (Sign) w10: v1(2105.36,8705.36) 2520,9120 v1(5000,9120)
  Int3 (Sign) w10: v1(5000,9120) P1B.21@5000,9850
NetBT1_1: BT1.1 J3.1 J3.2 | length 1119.5
  Top Layer w20: J3.1@628.74,750 J3.2@628.74,828.74 1043.23,1243.23 BT1.1@1043.23,1660 BT1.1@1070,1686.77
NetBT1_2: BT1.2 J3.3 J3.4 | length 2315.8
  Top Layer w20: J3.4@550,828.74 J3.3@550,750 555.21,744.79 555.21,714.79 580,690 800,690 1300,1190 1920,1190 2196.77,1466.77 BT1.2@2196.77,1660 BT1.2@2220,1683.23
NetC1A_2: C1A.2 TP19A.1 U3A.1 | length 228
  Top Layer w10: C1A.2@3600,10086.42 TP19A.1@3600,10175
  Top Layer w30: U3A.1@3465.55,10094.09 3465.55,10091.1 3470.24,10086.42 C1A.2@3600,10086.42
NetC1B_2: C1B.2 TP19B.1 U3B.1 | length 228
  Top Layer w10: C1B.2@3600,7036.42 TP19B.1@3600,7125
  Top Layer w30: U3B.1@3465.55,7044.09 3465.55,7041.1 3470.24,7036.42 C1B.2@3600,7036.42
NetC1C_2: C1C.2 TP19C.1 U3C.1 | length 228
  Top Layer w10: C1C.2@3600,7986.42 TP19C.1@3600,8075
  Top Layer w30: U3C.1@3465.55,7994.09 3465.55,7991.1 3470.24,7986.42 C1C.2@3600,7986.42
NetC1D_2: C1D.2 TP19D.1 U3D.1 | length 228
  Top Layer w10: C1D.2@3600,9136.42 TP19D.1@3600,9225
  Top Layer w30: U3D.1@3465.55,9144.09 3465.55,9141.1 3470.24,9136.42 C1D.2@3600,9136.42
NetC2A_2: C2A.2 C3A.1 C4A.1 TP20A.1 U1A.4 U2A.4 U3A.3 | length 1426.2
  Top Layer w10: 2175,10010 U2A.4@2175,10090.16 ; 2675,9992.91 U1A.4@2675,10090.16 ; C2A.2@3150,10086.42 TP20A.1@3150,10175
  Top Layer w20: 2175,10010 2192.09,9992.91 C4A.1@2400,9992.91
  Top Layer w30: C4A.1@2400,9992.91 2675,9992.91 C3A.1@2900,9992.91 3000.12,9992.91 3093.05,10085.84 3149.42,10085.84 C2A.2@3150,10086.42 3279.76,10086.42 3284.45,10091.1 U3A.3@3284.45,10094.09
NetC2B_2: C2B.2 C3B.1 C4B.1 TP20B.1 U1B.4 U2B.4 U3B.3 | length 1428.2
  Top Layer w10: 2175,6960 U2B.4@2175,7040.16 ; 2670,6942.91 2675,6947.91 U1B.4@2675,7040.16 ; C2B.2@3150,7036.42 TP20B.1@3150,7125
  Top Layer w20: 2175,6960 2192.09,6942.91 C4B.1@2400,6942.91
  Top Layer w30: C4B.1@2400,6942.91 2670,6942.91 C3B.1@2900,6942.91 3000.12,6942.91 3093.05,7035.84 3149.42,7035.84 C2B.2@3150,7036.42 3279.76,7036.42 3284.45,7041.1 U3B.3@3284.45,7044.09
NetC2C_2: C2C.2 C3C.1 C4C.1 TP20C.1 U1C.4 U2C.4 U3C.3 | length 1426.2
  Top Layer w10: 2175,7910 U2C.4@2175,7990.16 ; 2675,7892.91 U1C.4@2675,7990.16 ; C2C.2@3150,7986.42 TP20C.1@3150,8075
  Top Layer w20: 2175,7910 2192.09,7892.91 C4C.1@2400,7892.91
  Top Layer w30: C4C.1@2400,7892.91 2675,7892.91 C3C.1@2900,7892.91 3000.12,7892.91 3093.05,7985.84 3149.42,7985.84 C2C.2@3150,7986.42 3279.76,7986.42 3284.45,7991.1 U3C.3@3284.45,7994.09
NetC2D_2: C2D.2 C3D.1 C4D.1 TP20D.1 U1D.4 U2D.4 U3D.3 | length 1426.2
  Top Layer w10: 2175,9060 U2D.4@2175,9140.16 ; 2675,9042.91 U1D.4@2675,9140.16 ; C2D.2@3150,9136.42 TP20D.1@3150,9225
  Top Layer w20: 2175,9060 2192.09,9042.91 C4D.1@2400,9042.91
  Top Layer w30: C4D.1@2400,9042.91 2675,9042.91 C3D.1@2900,9042.91 3000.12,9042.91 3093.05,9135.84 3149.42,9135.84 C2D.2@3150,9136.42 3279.76,9136.42 3284.45,9141.1 U3D.3@3284.45,9144.09
NetJ19_1: J19.1 P2A.15 | length 3142.2
  Int2 (Sign) w10: P2A.15@4700,3450 5405,2745 5405,1435 4970,1000 J19.1@4750,1000
NetP1A_6: P1A.6 R2.1 | length 240.5
  Bottom Layer w10: P1A.6@4200,8610 R2.1@4200,8850.47
NetP1A_7: P1A.7 R3.1 | length 240.5
  Bottom Layer w10: R3.1@4300,8259.53 P1A.7@4300,8500
NetP1A_8: P1A.8 R4.1 | length 240.5
  Bottom Layer w10: P1A.8@4300,8610.47 R4.1@4300,8850.94
NetP1A_12: P1A.12 R5.1 | length 240.5
  Bottom Layer w10: P1A.12@4500,8600 R5.1@4500,8840.47
NetP1A_13: P1A.13 R6.1 | length 240.5
  Bottom Layer w10: R6.1@4600,8259.53 P1A.13@4600,8500
NetP1A_14: P1A.14 R7.1 | length 240.5
  Bottom Layer w10: P1A.14@4600,8600 R7.1@4600,8840.47
NetP1A_15: P1A.15 R8.1 | length 240.5
  Bottom Layer w10: R8.1@4700,8259.06 P1A.15@4700,8499.53
NetP1A_16: P1A.16 R9.1 | length 240.5
  Bottom Layer w10: P1A.16@4700,8600.47 R9.1@4700,8840.94
NetP1A_17: P1A.17 R10.1 | length 240.5
  Bottom Layer w10: R10.1@4800,8259.06 P1A.17@4800,8499.53
NetP1A_18: P1A.18 R11.1 | length 240.5
  Bottom Layer w10: P1A.18@4800,8600.47 R11.1@4800,8840.94
NetP1A_21: P1A.21 R12.1 | length 240.5
  Bottom Layer w10: R12.1@5000,8259.53 P1A.21@5000,8500
NetP1A_38: P1A.38 R24.1 | length 240.5
  Bottom Layer w10: P1A.38@5800,8600 R24.1@5800,8840.47
NetP1B_22: P1B.22 R13.2 | length 240.9
  Bottom Layer w10: P1B.22@5000,9950 R13.2@5000,10190.94
NetP1B_23: P1B.23 R14.2 | length 240.5
  Bottom Layer w10: R14.2@5100.33,9604.02 P1B.23@5100.33,9844.49
NetP1B_24: P1B.24 R15.2 | length 240.9
  Bottom Layer w10: P1B.24@5100,9949.53 R15.2@5100,10190.47
NetP1B_25: P1B.25 R16.2 | length 240.5
  Bottom Layer w10: R16.2@5200.33,9603.54 P1B.25@5200.33,9844.02
NetP1B_26: P1B.26 R17.2 | length 240.9
  Bottom Layer w10: P1B.26@5200,9949.53 R17.2@5200,10190.47
NetP1B_27: P1B.27 R18.2 | length 240.5
  Bottom Layer w10: R18.2@5300.33,9604.02 P1B.27@5300.33,9844.49
NetP1B_28: P1B.28 R19.2 | length 240.9
  Bottom Layer w10: P1B.28@5300,9949.53 R19.2@5300,10190.47
NetP1B_34: P1B.34 R20.2 | length 240.9
  Bottom Layer w10: P1B.34@5600,9949.53 R20.2@5600,10190.47
NetP1B_35: P1B.35 R21.2 | length 240.5
  Bottom Layer w10: R21.2@5700.33,9604.02 P1B.35@5700.33,9844.49
NetP1B_36: P1B.36 R22.2 | length 240.9
  Bottom Layer w10: P1B.36@5700,9949.53 R22.2@5700,10190.47
NetP1B_37: P1B.37 R23.2 | length 240.5
  Bottom Layer w10: R23.2@5800.33,9604.02 P1B.37@5800.33,9844.49
NetP1B_38: P1B.38 R25.2 | length 240.9
  Bottom Layer w10: P1B.38@5800,9949.53 R25.2@5800,10190.47
NetR1_2: R1.2 TP17D.1 U1D.12 | length 429.1
  Top Layer w10: TP17D.1@2700,8775 TP17D.1@2700.3,8775.3 ; U1D.12@2700.59,8909.84 2700.3,8909.55 TP17D.1@2700.3,8775.3 ; R1.2@2745.47,8500 2745.47,8615.12 2700.3,8660.3 TP17D.1@2700.3,8775.3
NetR26_2: R26.2 TP13D.1 U1D.10 | length 429.3
  Top Layer w10: R26.2@2604.53,8500 2604.53,8564.53 2650.3,8610.3 TP13D.1@2650.3,8825.3 ; U1D.10@2649.41,8909.84 2649.7,8909.55 2649.7,8825.3 TP13D.1@2650,8825
NetR27_2: R27.2 TP9D.1 U1D.5 | length 403.6
  Top Layer w10: R27.2@2604.53,9525 2604.53,9465.47 2650,9420 2650,9226.18 TP9D.1@2650.59,9225.59 ; U1D.5@2649.41,9140.16 2649.7,9140.45 2649.7,9224.7 TP9D.1@2650,9225
NetR28_2: R28.2 TP5D.1 U1D.3 | length 403.5
  Top Layer w10: TP5D.1@2700,9275 2700.3,9274.7 2700.3,9140.45 U1D.3@2700.59,9140.16 ; TP5D.1@2700.74,9275.74 2700,9276.48 2700,9416 2745.47,9461.47 R28.2@2745.47,9525
NetR29_2: R29.2 TP18D.1 U2D.12 | length 439.5
  Top Layer w10: TP18D.1@2200,8775 TP18D.1@2200.3,8775.3 ; U2D.12@2200.59,8909.84 2200.3,8909.55 TP18D.1@2200.3,8775.3 ; R29.2@2270.47,8500 2270.47,8590.12 2200.3,8660.3 TP18D.1@2200.3,8775.3
NetTP3D_1: TP3D.1 TP22.1 U1D.1 U1D.2 | length 278.6
  Top Layer w10: U1D.2@2726.18,9140.16 U1D.1@2751.77,9140.16 2751.77,9170.71 2750,9172.48 TP3D.1@2750,9225 2750,9345.08 2780,9375.08 TP22.1@2780,9380
NetTP7D_1: TP7D.1 TP23.1 U1D.6 U1D.7 | length 337.7
  Top Layer w10: TP23.1@2500,9375 2560.36,9375 2600.36,9335 TP7D.1@2600.36,9275.36 ; TP7D.1@2600,9275 2600,9172.48 2598.23,9170.71 U1D.7@2598.23,9140.16 U1D.6@2623.82,9140.16
NetTP11D_1: TP11D.1 TP24.1 U1D.8 U1D.9 | length 352.6
  Top Layer w10: TP24.1@2500,8625 2500,8675 TP11D.1@2600,8775 2600,8877.52 2598.23,8879.29 U1D.8@2598.23,8909.84 U1D.9@2623.82,8909.84
NetTP15B_1: TP15B.1 U1B.13 U1B.14 | length 233.2
  Top Layer w10: U1B.13@2726.18,6809.84 U1B.14@2751.77,6809.84 2751.05,6809.12 2751.05,6726.05 TP15B.1@2750,6725 2752.5,6722.5 2752.5,6607.5 v1(2755,6605)
NetTP15D_1: TP15D.1 TP25.1 U1D.13 U1D.14 | length 332.1
  Top Layer w10: U1D.13@2726.18,8909.84 U1D.14@2751.77,8909.84 2751.05,8909.12 2751.05,8826.05 TP15D.1@2750,8825 ; TP15D.1@2750.36,8825.36 2752.61,8823.12 2752.61,8708.12 2790.09,8670.64 2790.09,8634.91 TP25.1@2800,8625
NetTP16D_1: TP16D.1 TP21.1 U2D.13 U2D.14 | length 267.2
  Top Layer w10: U2D.13@2226.18,8909.84 U2D.14@2251.77,8909.84 2251.77,8879.29 2250,8877.52 TP16D.1@2250,8825 2325,8750 TP21.1@2375,8750
NetTP17B_1: TP17B.1 U1B.12 | length 264.2
  Top Layer w10: U1B.12@2700.59,6809.84 2700.3,6809.55 2700.3,6675.3 TP17B.1@2700,6675 2700,6587.5 2705.22,6582.28 2705.22,6554.78 v1(2710,6550)
SYS_24V: J1.56 J1.58 J1.60 J1.62 J1.64 TP1.1 TP2.1 | length 1118.2
  Bottom Layer w20: TP2.1@375,11375 TP1.1@625,11375 625,11475 850,11700 J1.64@900,11700 J1.62@1000,11700 J1.60@1100,11700 J1.58@1200,11700 J1.56@1300,11700
pads on no net: J3.MT1 J3.MT2 J5.MT1 J5.MT2 MH1.1 MH2.1 MH3.1 MH4.1 MH5.1 MH6.1 MH7.1 MH8.1 MH9.1 MH10.1 MH11.1

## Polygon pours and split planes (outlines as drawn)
GND on Bottom Layer "NONET_L06_P-001" (solid, remove dead copper, pour order 1): 0,12000 7000,12000 7000,0 0,0
no net on Top Overlay "NONET_L-01_P-001" (solid, pour order 4): 240,6660 380,6660 380,5950 240,5950
GND on Top Layer "NONET_L06_P-001" (solid, remove dead copper, pour order 0): 0,12000 7000,12000 7000,0 0,0
GND on Int3 (Sign) "NONET_L06_P-001" (solid, remove dead copper, pour order 3): 0,12000 7000,12000 7000,0 0,0
GND on Int2 (Sign) "NONET_L06_P-001" (solid, remove dead copper, pour order 2): 0,12000 7000,12000 7000,0 0,0
GND on Int4 (GND2) (split plane): 6979.9,20.1 20.1,20.1 20.1,11979.9 6979.9,11979.9
GND on Int1 (GND) (split plane): 6979.9,20.1 20.1,20.1 20.1,11979.9 6979.9,11979.9

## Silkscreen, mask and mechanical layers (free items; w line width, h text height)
Top Overlay:
  drawing of 9 lines, arcs and shapes, not listed
  text "64" at 735,11685 h30
  text "2" at 4087.41,11684.95 h30
  text "63" at 733.15,11576.6 h30
  text "1" at 4085.56,11576.55 h30
  text "GND" at 6232,11283.07 h30 r45
  text "GND" at 2535,11275 h30 r90
  text "MEDIA_EN" at 2626.66,11272.95 h30 r90
  text "SYS_24V" at 920,11265 h30 r90
  text "SYS_24V" at 1020,11265 h30 r90
  text "SYS_24V" at 1120,11265 h30 r90
  text "SYS_24V" at 1220,11265 h30 r90
  text "SYS_24V" at 1330,11265 h30 r90
  text "GND" at 1435,11265 h30 r90
  text "HPB_TEMP4" at 1530,11265 h30 r90
  text "HPB_TEMP3" at 1630,11265 h30 r90
  text "HPB_TEMP2" at 1730,11265 h30 r90
  text "HPB_TEMP1" at 1830,11265 h30 r90
  text "HPB_TEMP0" at 1920,11265 h30 r90
  text "HPB_VICR3" at 2030,11265 h30 r90
  text "IPB2_TEMP" at 2330,11265 h30 r90
  text "GND" at 2725,11265 h30 r90
  text "I2C_SCL" at 2820,11265 h30 r90
  text "GND" at 2925,11265 h30 r90
  text "I2C_SDA" at 3030,11265 h30 r90
  text "GND" at 3125,11265 h30 r90
  text "SIC_3V3" at 3220,11265 h30 r90
  text "SPARE7" at 3325,11265 h30 r90
  text "SPARE6" at 3425,11265 h30 r90
  text "SPARE5" at 3525,11265 h30 r90
  text "SPARE4" at 3625,11265 h30 r90
  text "SPARE3" at 3725,11265 h30 r90
  text "SPARE2" at 3825,11265 h30 r90
  text "SPARE1" at 3915,11265 h30 r90
  text "SPARE0" at 4025,11265 h30 r90
  text "HPB_VICR2" at 2126.66,11262.95 h30 r90
  text "HPB_VICR1" at 2226.66,11262.95 h30 r90
  text "IPB1_TEMP" at 2426.66,11262.95 h30 r90
  text "24V" at 450,11247.07 h30 r45
  text "24V" at 680,11237.07 h30 r45
  text "GND" at 5630,11227.07 h30 r45
  text "GND" at 5910,11227.07 h30 r45
  text "BAYCAT I2C" at 55,11145 h30 r270
  text "GND" at 895,11135 h30 r270
  text "GND" at 998.46,11134.64 h30 r270
  text "GND" at 1098.46,11134.64 h30 r270
  text "GND" at 1205,11135 h30 r270
  text "GND" at 1305,11135 h30 r270
  text "SYNCBOX_EN" at 1400,11135 h30 r270
  text "CISCO2_EN" at 1500,11135 h30 r270
  text "CISCO1_EN" at 1600,11135 h30 r270
  text "IPB2_CHD_FET_EN" at 1700,11135 h30 r270
  text "IPB1_CHD_FET_EN" at 1800,11135 h30 r270
  text "IPB2_CHD_RLY_EN" at 1900,11135 h30 r270
  text "IPB1_CHD_RLY_EN" at 2000,11135 h30 r270
  text "IPB2_CHC_FET_EN" at 2100,11135 h30 r270
  text "IPB1_CHC_FET_EN" at 2200,11135 h30 r270
  text "IPB2_CHC_RLY_EN" at 2300,11135 h30 r270
  text "IPB1_CHC_RLY_EN" at 2400,11135 h30 r270
  text "IPB2_CHB_FET_EN" at 2500,11135 h30 r270
  text "IPB1_CHB_FET_EN" at 2600,11135 h30 r270
  text "IPB2_CHB_RLY_EN" at 2700,11135 h30 r270
  text "IPB1_CHB_RLY_EN" at 2800,11135 h30 r270
  text "IPB2_CHA_FET_EN" at 2900,11135 h30 r270
  text "IPB1_CHA_FET_EN" at 3000,11135 h30 r270
  text "IPB2_CHA_RLY_EN" at 3100,11135 h30 r270
  text "IPB1_CHA_RLY_EN" at 3200,11135 h30 r270
  text "IPB2_CHD_CURRENT_SET" at 3300,11135 h30 r270
  text "IPB1_CHD_CURRENT_SET" at 3400,11135 h30 r270
  text "IPB2_CHC_CURRENT_SET" at 3500,11135 h30 r270
  text "IPB1_CHC_CURRENT_SET" at 3600,11135 h30 r270
  text "IPB2_CHB_CURRENT_SET" at 3700,11135 h30 r270
  text "IPB1_CHB_CURRENT_SET" at 3800,11135 h30 r270
  text "IPB2_CHA_CURRENT_SET" at 3900,11135 h30 r270
  text "IPB1_CHA_CURRENT_SET" at 4000,11135 h30 r270
  text "BAYCAT I2C" at 635,11125 h30 r270
  text "GND" at 6222,11013.07 h30 r45
  text "2" at 3857.41,9934.95 h30
  text "40" at 5977.41,9934.95 h30
  text "39" at 5977.41,9826.55 h30
  text "1" at 3865,9825 h30
  text "BRN" at 4015,9610 h40 r90
  text "RED" at 4115,9610 h40 r90
  text "ORG" at 4215,9610 h40 r90
  text "YEL" at 4315,9610 h40 r90
  text "BLK" at 5915,9610 h40 r90
  text "40" at 5977.41,8594.95 h30
  text "2" at 3857.41,8584.95 h30
  text "39" at 5977.41,8486.55 h30
  text "1" at 3865,8475 h30
  text "BRN" at 4015,8260 h40 r90
  text "RED" at 4115,8260 h40 r90
  text "ORG" at 4215,8260 h40 r90
  text "YEL" at 4315,8260 h40 r90
  text "BLK" at 5915,8260 h40 r90
  text "SN:" at 294.59,6834.81 h60 r270
  text "CAGE: .Gbl_Cage" at 512,6688 h60 r270
  text "DATE: .Gbl_DSN_APP_DATE" at 612,6688 h60 r270
  text "PN: .Gbl_PCB_DWG_NO" at 712,6688 h60 r270
  text "ENG:  .Gbl_Engineer" at 812,6688 h60 r270
  text "REV: .Gbl_Revision" at 912,6688 h60 r270
  text "MARS2 BREAKOUT BOARD" at 1012,6688 h60 r270
  text "26" at 5295,3545 h30
  text "2" at 3852.41,3543.3 h30
  text "10" at 6195,3541.65 h30
  text "2" at 5552.41,3539.95 h30
  text "25" at 5295,3445 h30
  text "9" at 6195,3441.65 h30
  text "1" at 3860,3433.35 h30
  text "1" at 5560,3430 h30
  text "BRN" at 4015,3210 h40 r90
  text "RED" at 4115,3210 h40 r90
  text "ORG" at 4215,3210 h40 r90
  text "YEL" at 4315,3210 h40 r90
  text "BLU" at 5215,3210 h40 r90
  text "BRN" at 5715,3210 h40 r90
  text "RED" at 5815,3210 h40 r90
  text "ORG" at 5915,3210 h40 r90
  text "BLK" at 6115,3210 h40 r90
  text "26" at 5295,2195 h30
  text "2" at 3852.41,2193.3 h30
  text "10" at 6195,2191.65 h30
  text "2" at 5552.41,2189.95 h30
  text "25" at 5295,2095 h30
  text "9" at 6195,2091.65 h30
  text "1" at 3860,2083.35 h30
  text "1" at 5560,2080 h30
  text "BRN" at 4015,1860 h40 r90
  text "RED" at 4115,1860 h40 r90
  text "ORG" at 4215,1860 h40 r90
  text "YEL" at 4315,1860 h40 r90
  text "BLU" at 5215,1860 h40 r90
  text "BRN" at 5715,1860 h40 r90
  text "RED" at 5815,1860 h40 r90
  text "ORG" at 5915,1860 h40 r90
  text "BLK" at 6115,1860 h40 r90
  text "24V_UNSWITCHED_BUS_I" at 3180,1529.11 h30 r270
  text "HCB_MEDIA_CURRENT" at 880,1449.84 h30 r270
  text "HPB_CISCO1_I" at 3990,1345 h30 r270
  text "HPB_SYNCBOX_I" at 3580,1324.17 h30 r270
  text "HPB_ISO24V_I" at 3390,1289.18 h30 r270
  text "HPB_CISCO2_I" at 3790,1289.18 h30 r270
  text "FAULT_MUX_A" at 1179.22,1278.99 h30 r270
  text "FAULT_MUX_C" at 980,1274.9 h30 r270
  text "FAULT_MUX_B" at 1087.52,1272.58 h30 r270
  text "IPB1_RESET" at 2280.06,1238.46 h30 r270
  text "IPB2_RESET" at 2180.19,1233.59 h30 r270
  text "HPB_24V_V" at 2980,1214.21 h30 r270
  text "HPB_24V_I" at 2780,1204.92 h30 r270
  text "HPB_5V_V" at 2580.06,1188.47 h30 r270
  text "HPB_5V_I" at 2380.06,1178.48 h30 r270
  text "MVC_L_V" at 1379.22,1149.03 h30 r270
  text "MVC_R_V" at 1579.22,1149.03 h30 r270
  text "MVC_L_I" at 1779.22,1139.03 h30 r270
  text "MVC_R_I" at 1980.19,1138.62 h30 r270
  text "BATTERY BACKUP" at 725,1065 h30 r270
  text "GND" at 1483.76,1049.75 h30 r270
  text "GND" at 1683.76,1049.75 h30 r270
  text "GND" at 1883.76,1049.75 h30 r270
  text "GND" at 2083.76,1049.75 h30 r270
  text "GND" at 2483.76,1049.75 h30 r270
  text "GND" at 2683.76,1049.75 h30 r270
  text "GND" at 2883.76,1049.75 h30 r270
  text "GND" at 3083.76,1049.75 h30 r270
  text "GND" at 3283.76,1049.75 h30 r270
  text "GND" at 3483.76,1049.75 h30 r270
  text "GND" at 3683.76,1049.75 h30 r270
  text "GND" at 3883.76,1049.75 h30 r270
  text "BATTERY BACKUP" at 65,1045 h30 r270
  text "GND" at 1285,1045 h30 r270
  text "GPIO_15" at 4586.47,960.61 h30 r45
  text "IN_FET_L_TEMP" at 860,852.97 h30 r270
  text "IN_FET_R_TEMP" at 960,852.97 h30 r270
  text "GF_SEL_ENn" at 3690,847.07 h30 r270
  text "GF_TEMP" at 1070,845 h30 r270
  text "IGB_TEMP" at 1180,845 h30 r270
  text "HCB_FAULT" at 1280,845 h30 r270
  text "IPB2_FAULT" at 1380,845 h30 r270
  text "IPB1_FAULT" at 1480,845 h30 r270
  text "GND" at 1575,845 h30 r270
  text "GF_SIG" at 1670,845 h30 r270
  text "GND" at 1775,845 h30 r270
  text "IPB2_CHD_I" at 1880,845 h30 r270
  text "GND" at 1975,845 h30 r270
  text "IPB1_CHD_I" at 2080,845 h30 r270
  text "GND" at 2175,845 h30 r270
  text "IPB2_CHC_I" at 2280,845 h30 r270
  text "GND" at 2375,845 h30 r270
  text "IPB1_CHC_I" at 2480,845 h30 r270
  text "GND" at 2575,845 h30 r270
  text "IPB2_CHB_I" at 2680,845 h30 r270
  text "GND" at 2775,845 h30 r270
  text "IPB1_CHB_I" at 2880,845 h30 r270
  text "GND" at 2975,845 h30 r270
  text "IPB2_CHA_I" at 3080,845 h30 r270
  text "GND" at 3175,845 h30 r270
  text "IPB1_CHA_I" at 3270,845 h30 r270
  text "GND" at 3375,845 h30 r270
  text "GF_CHS_EN" at 3480,845 h30 r270
  text "GF_NOD_EN" at 3590,845 h30 r270
  text "GF_SEL_C" at 3780,845 h30 r270
  text "GF_SEL_B" at 3880,845 h30 r270
  text "GF_SEL_A" at 3980,845 h30 r270
  text "GND" at 4650,767.07 h30 r45
  text "GND" at 4640,517.07 h30 r45
  text "64" at 735,385 h30
  text "2" at 4087.41,384.95 h30
  text "63" at 733.15,276.6 h30
  text "1" at 4085.56,276.55 h30
Top Assembly:
  lines w10: -2.72,0 5322.28,0 5322.28,12000 -2.72,12000 -2.72,0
